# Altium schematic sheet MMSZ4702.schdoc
size 127 x 101 mm
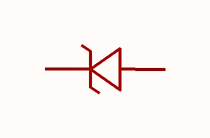
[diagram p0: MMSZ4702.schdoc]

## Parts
U?  mmsz4702  [SOD-123_L2.7-W1.6-LS3.7-RD]  (value not drawn)

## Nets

Not connected (* = marked no-connect by the designer): U? 1(K) 2(A)

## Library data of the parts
U? = mmsz4702: 二极管配置:1个独立式;稳压值(标称值):15V;稳压值(范围):14.25V~15.75V;耗散功率(Pd):350mW;; Manufacturer: CJ(江苏长电/长晶); AddInBom: yes; ModelId: ad7e39f9e5534b3c96ffdc5532ebb493; ModelName: SOD-123_L2.7-W1.6-H1.4-LS3.7; ModelTransform: 146.026,62.992,0,180,0,0,0.0005,0,0; Diode Configuration: 1个独立式; Zener Voltage(Nom): 15V; Reverse Leakage Current (Ir): 50nA; Pd - Power Dissipation: 350mW; Operating Junction Temperature Range: -55℃~+150℃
